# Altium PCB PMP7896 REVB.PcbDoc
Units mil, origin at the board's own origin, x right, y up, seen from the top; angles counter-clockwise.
Board outline 3850 x 3960 mil, 4 copper layers (Top Layer, MidLayer1, MidLayer2, Bottom Layer), stack 62.6 mil thick; 76 components, 29 nets, 152 pads, 108 vias.
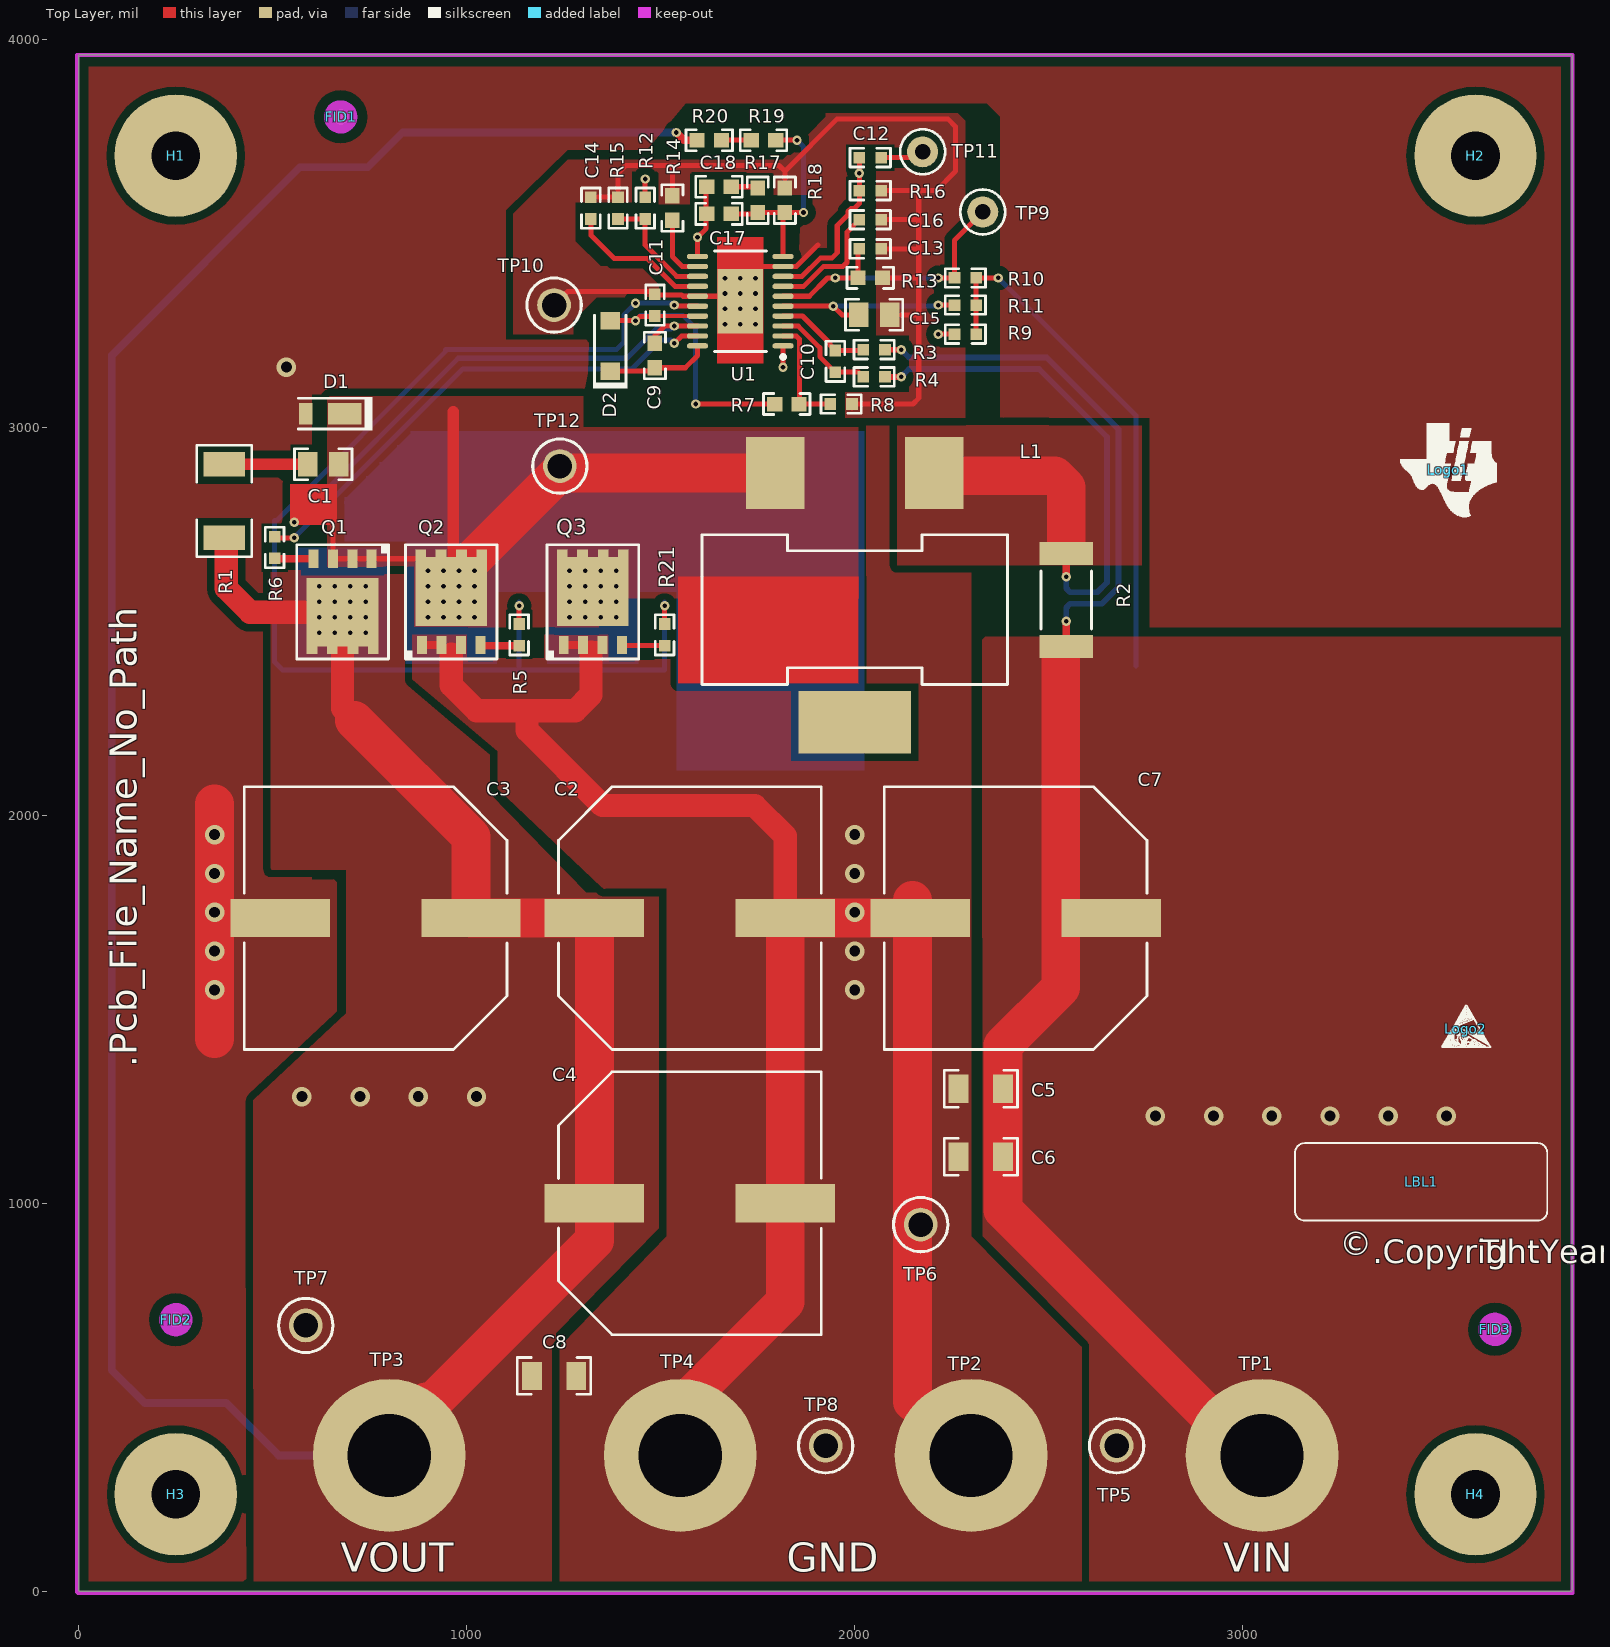
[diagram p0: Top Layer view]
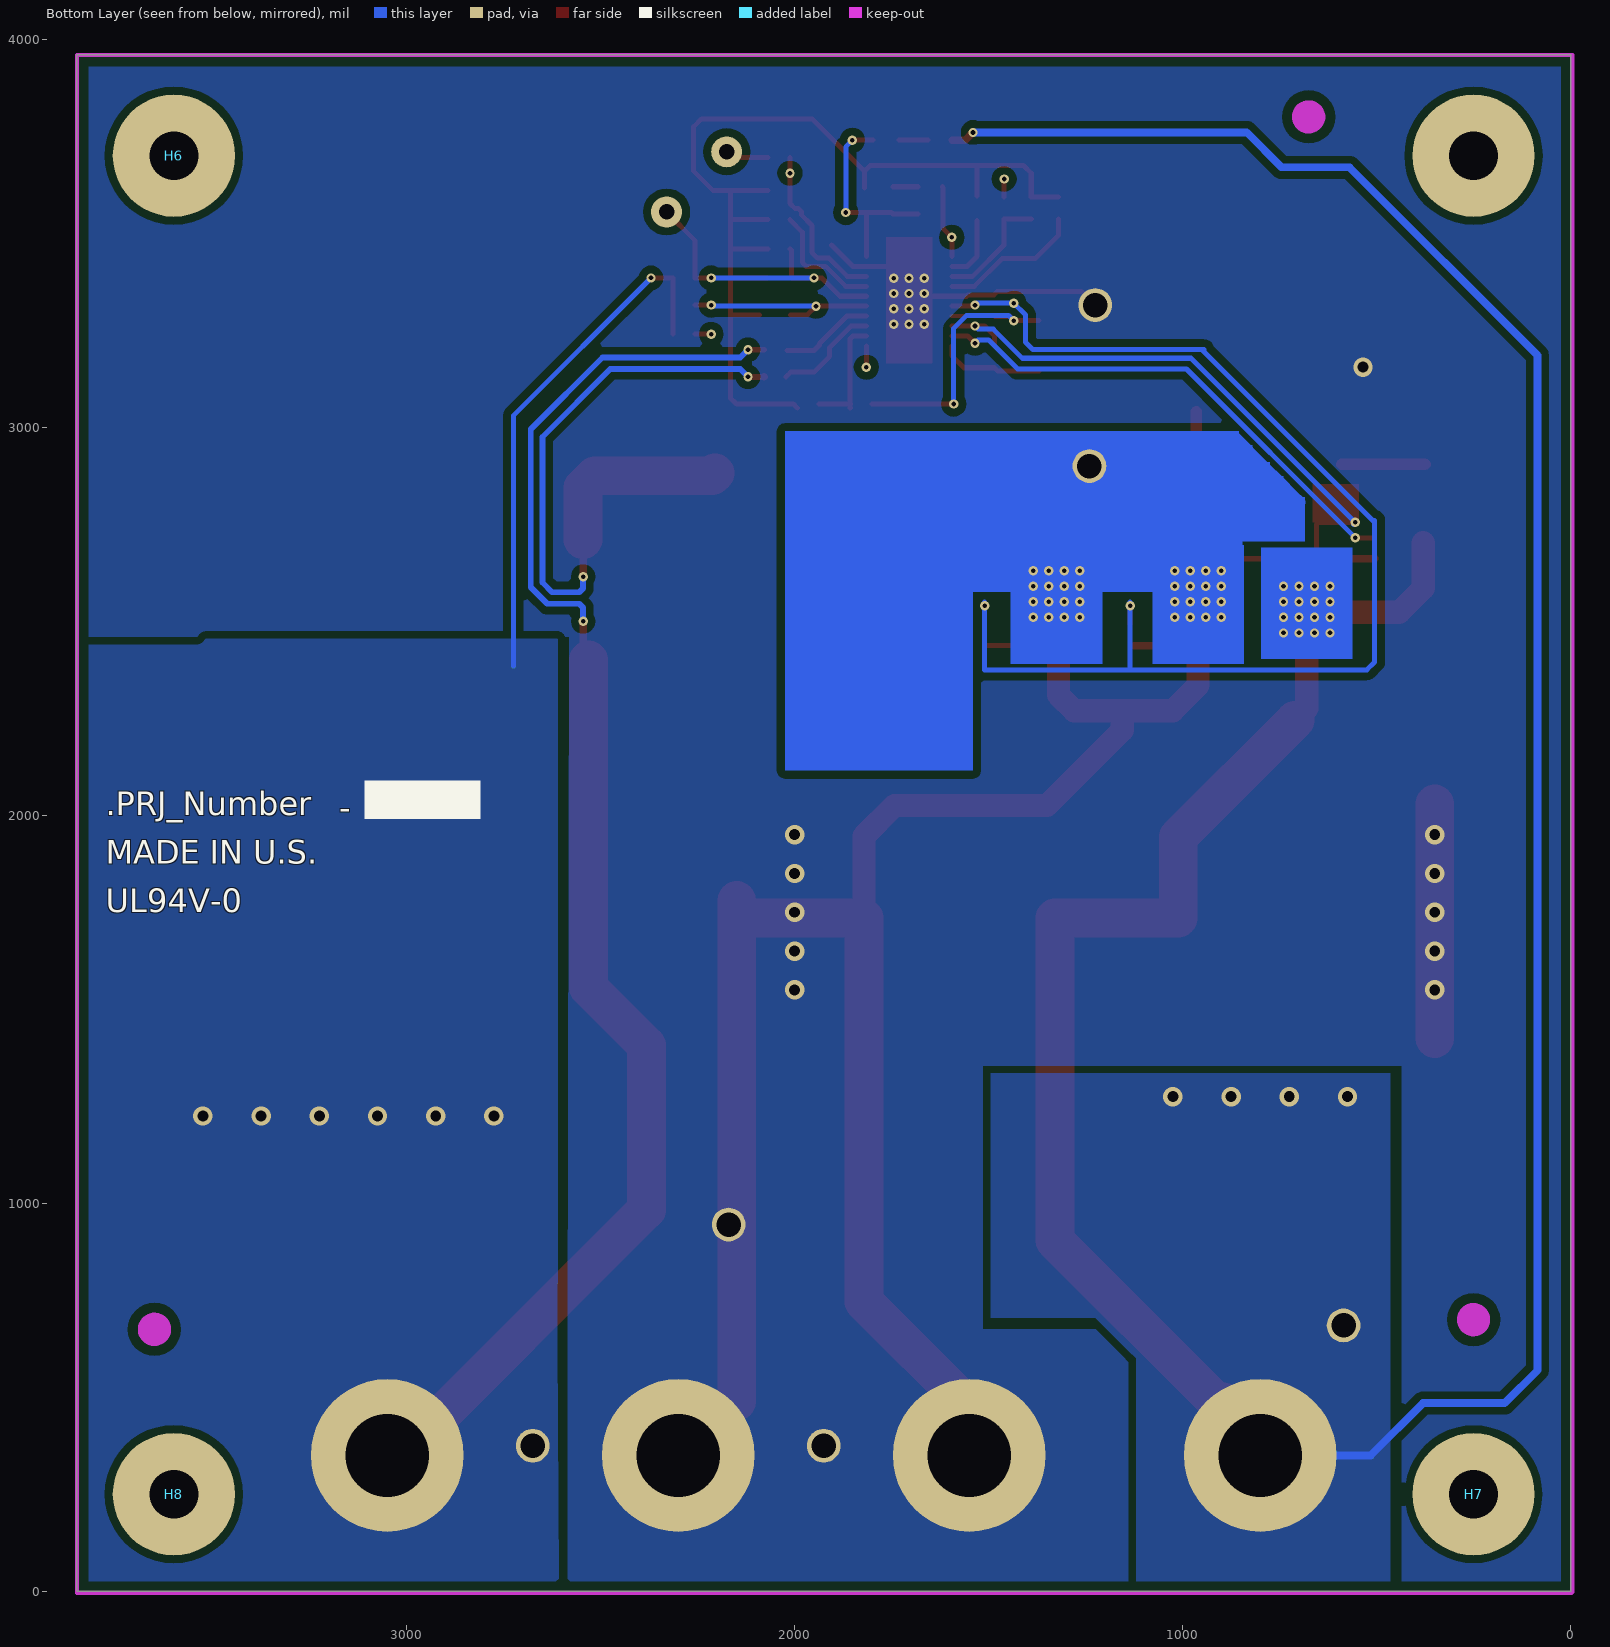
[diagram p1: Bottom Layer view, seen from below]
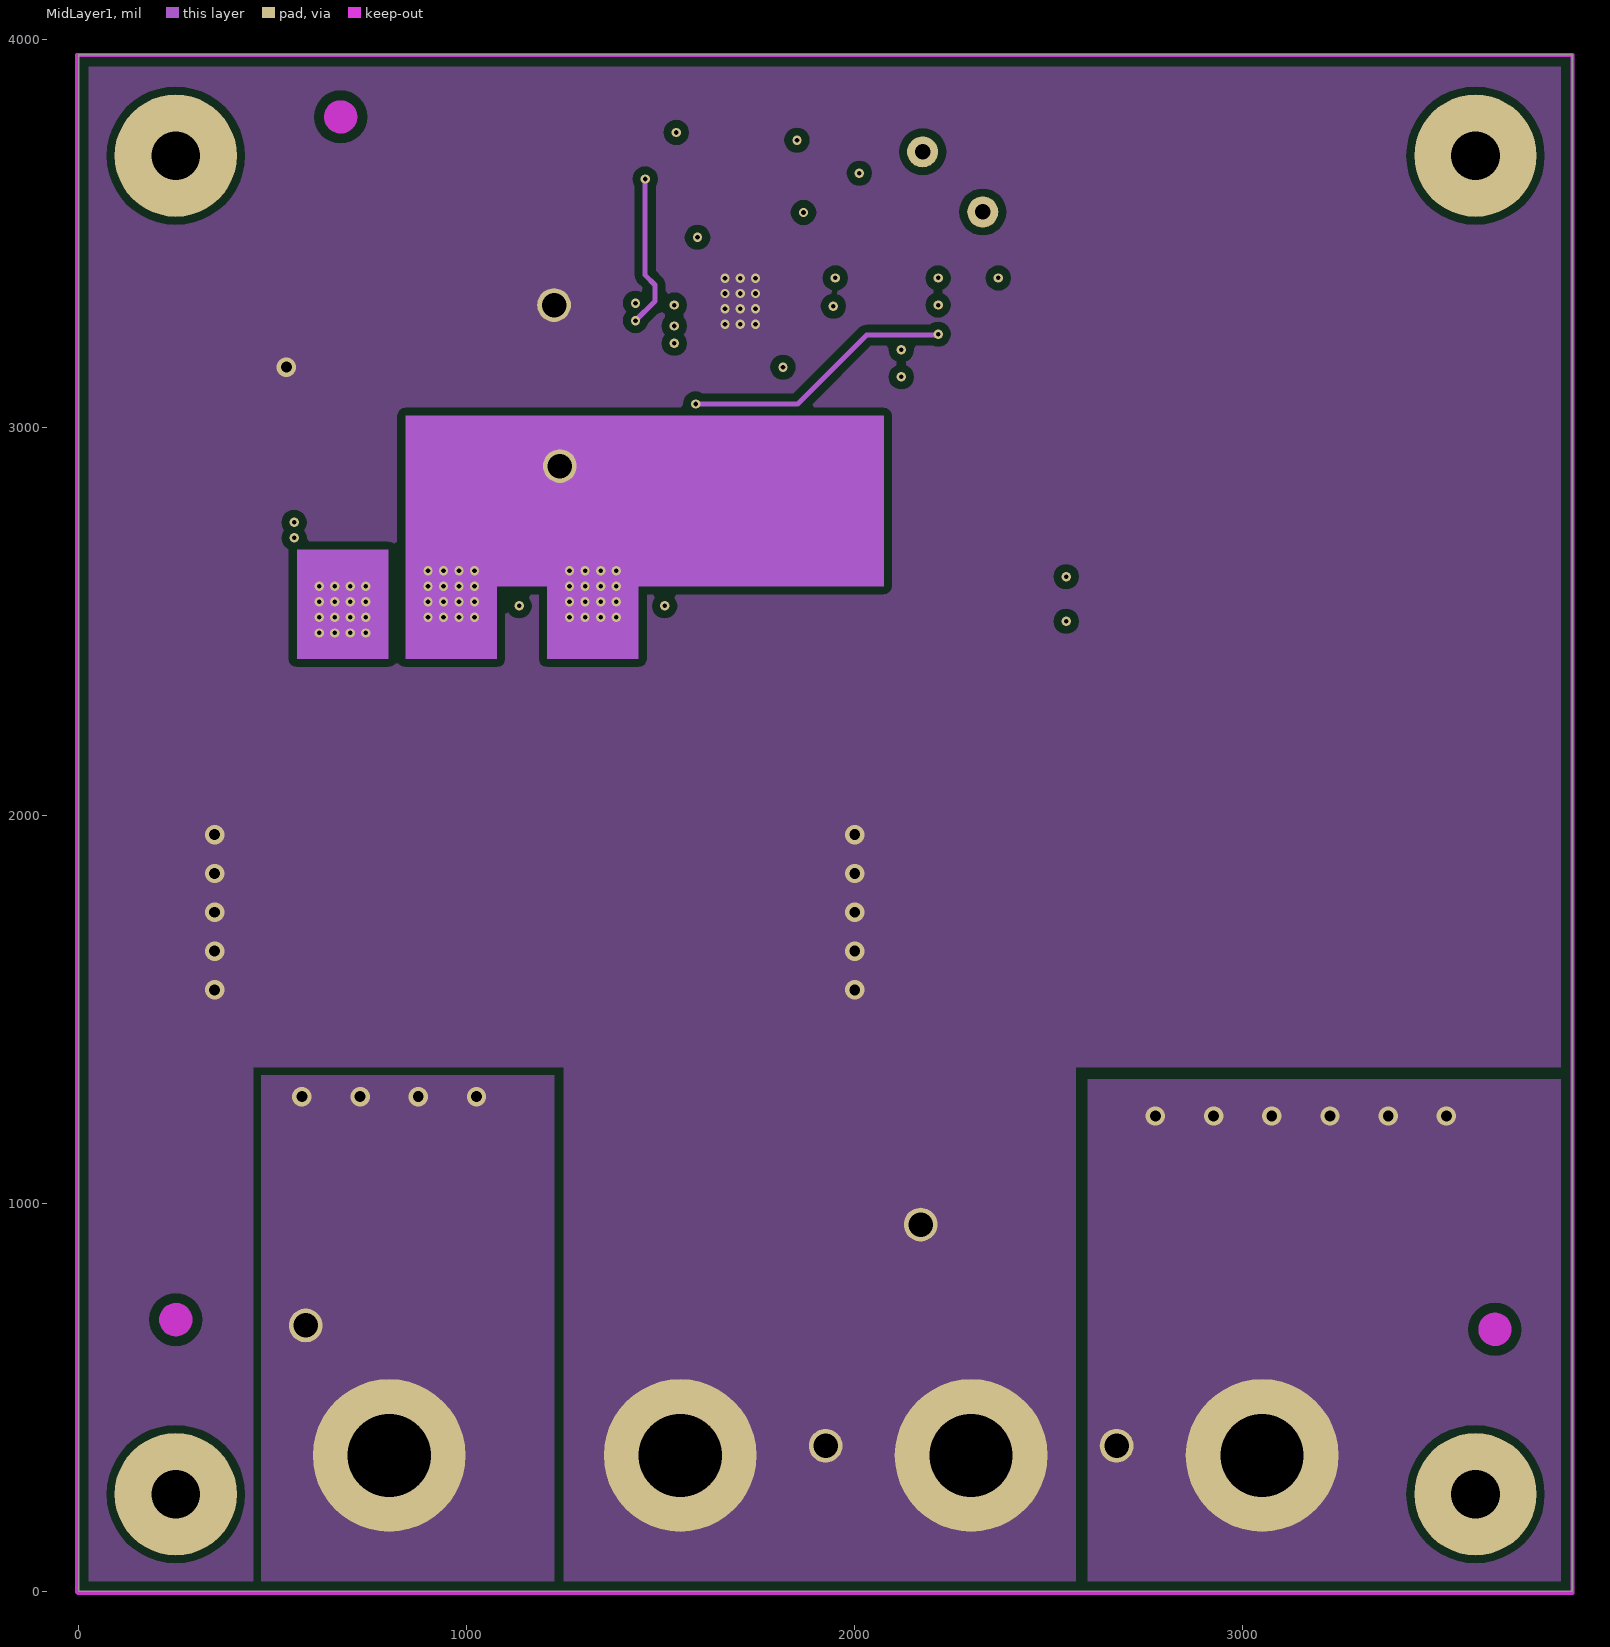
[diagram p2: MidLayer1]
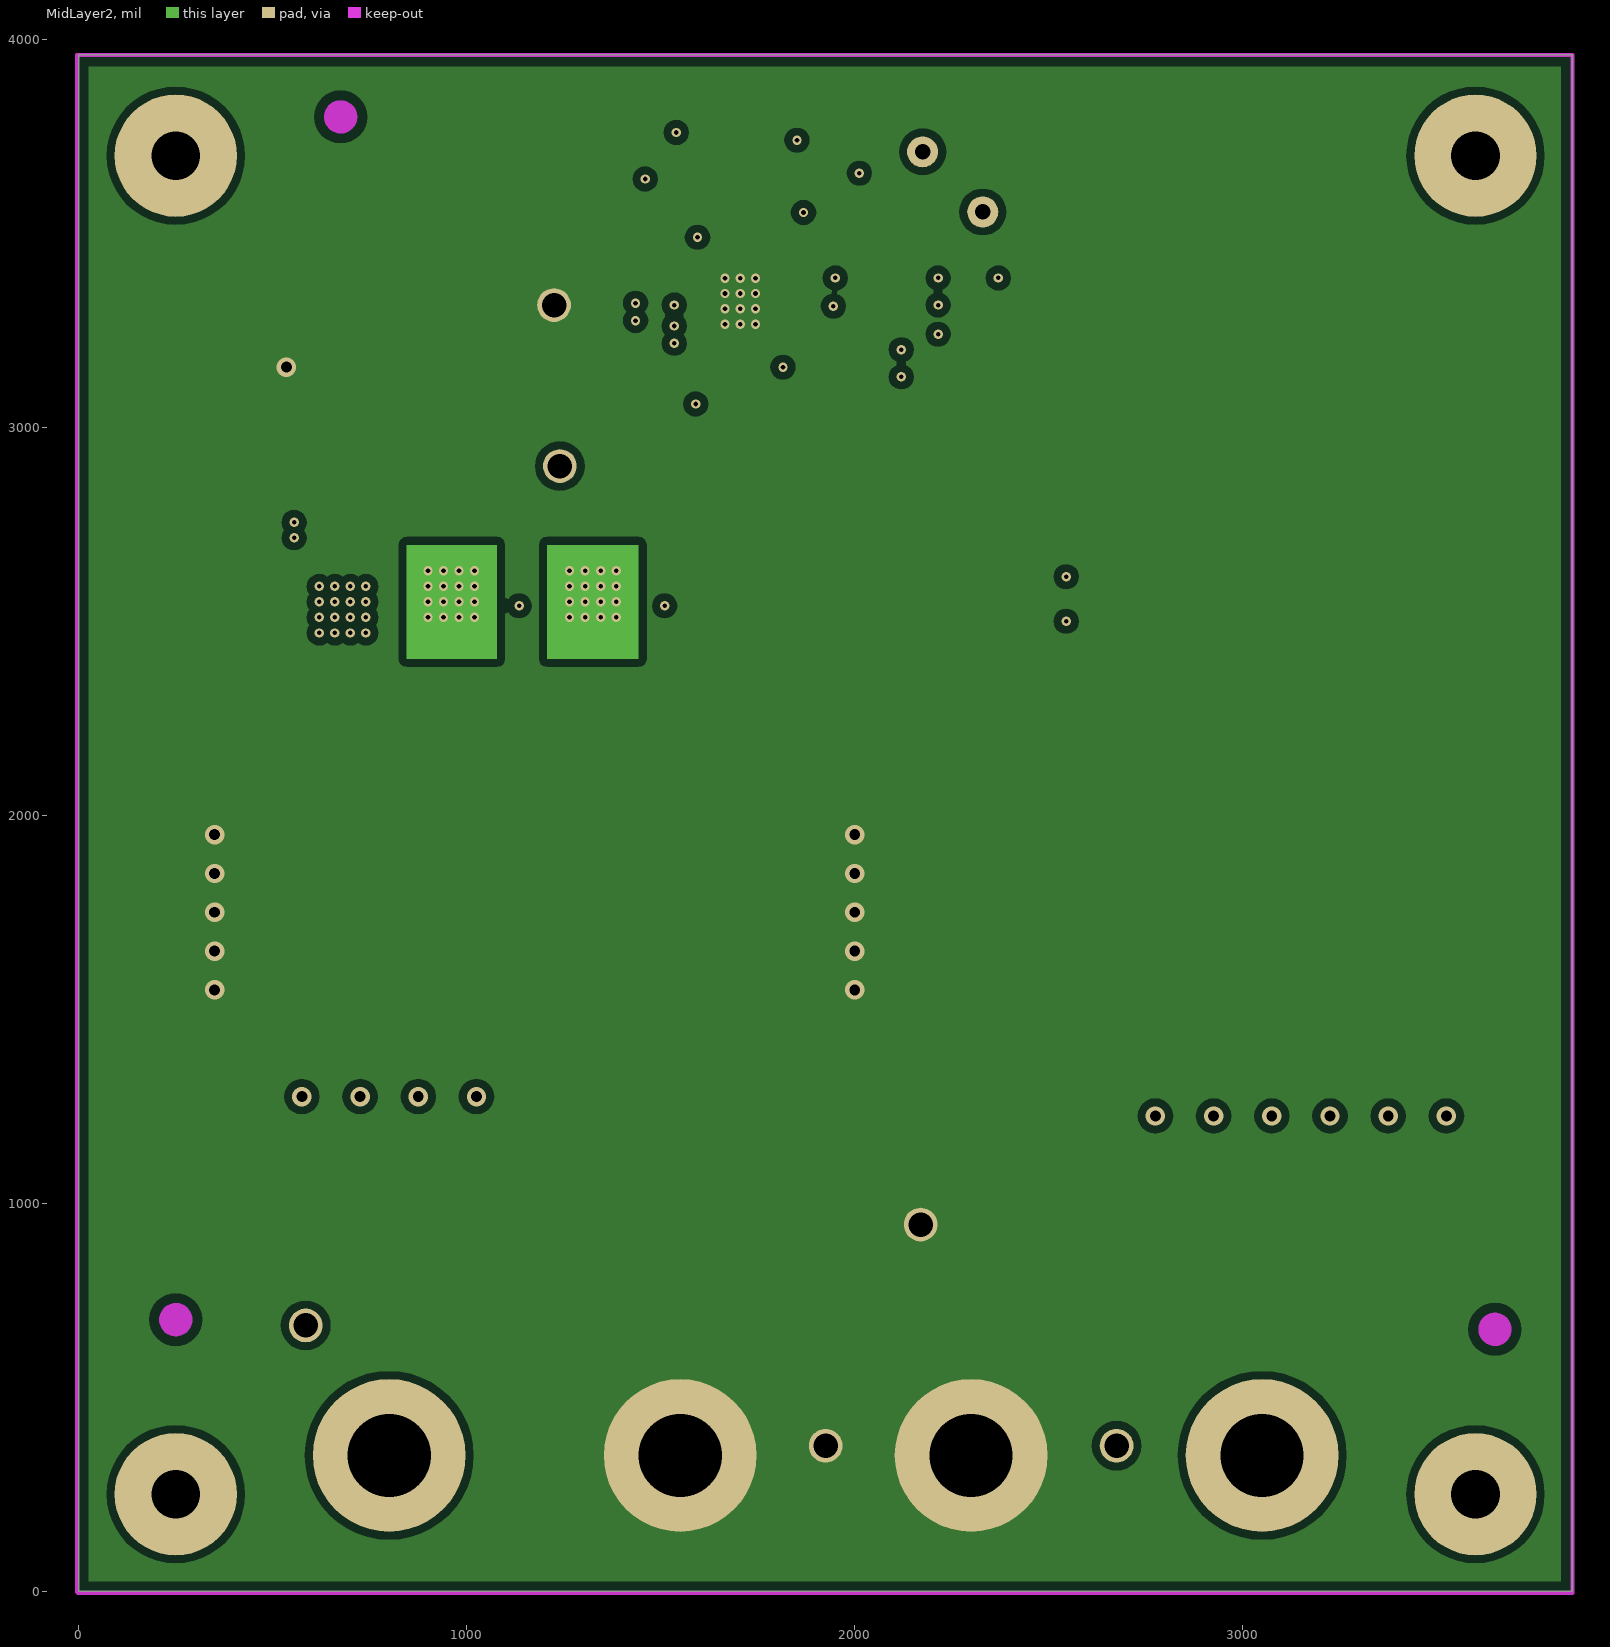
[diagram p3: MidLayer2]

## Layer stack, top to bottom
Top Layer: signal copper 1.4
Dielectric: prepreg 19, FR-4, Dk 4.8
MidLayer1: signal copper 1.4
Dielectric: core 19, FR-4, Dk 4.8
MidLayer2: signal copper 1.4
Dielectric: prepreg 19, FR-4, Dk 4.8
Bottom Layer: signal copper 1.4

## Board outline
0,0 0,3960 3850,3960 3850,0

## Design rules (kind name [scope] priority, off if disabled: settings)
AcuteAngle [All] p1: minimum=4.50000000000000E+0001 checktracksonly=FALSE
AssemblyTestPointUsage [All] p1: valid=2
Clearance Clearance_BoardEdge_MountingHoles [OnCopper and InComponentClass('Mounting Holes') vs IsKeepOut] p1: gap=40
Clearance Clearance_BoardEdge_Poly [OnCopper and InPoly vs IsKeepOut] p2: gap=25
Clearance Clearance_BoardEdge [OnCopper and Not InComponentClass('Logo') and not InComponentClass('FiducialMark') and not InRegion(1000,500,4000,800) vs IsKeepOut] p3: gap=75
Clearance Clearance_Polygon [IsRegion] p4: gap=20
Clearance [All] p5: gap=8
ComponentClearance ComponentClearance_Logo [InComponentClass(Logo)] p1: gap=50 collisioncheckmode=3 verticalgap=10 showdistances=FALSE
ComponentClearance ComponentClearance_ScrewToNut [(HasFootprint('NY PMS 440 0025 PH')) vs (HasFootprint('Keystone_1902C'))] p2: gap=5 collisioncheckmode=3 verticalgap=10 showdistances=FALSE
ComponentClearance ComponentClearance_MountingHoles [InComponentClass('Mounting Holes')] p3: gap=250 collisioncheckmode=3 verticalgap=100000 showdistances=FALSE
ComponentClearance ComponentClearance_SmallPassives [HasFootprint('0201*') or HasFootprint('0402*') or HasFootprint('0508') or HasFootprint('0603*') or HasFootprint('0612') or HasFootprint('0805*') or HasFootprint('0815*') or HasFootprint('0830*') or HasFootprint('1206*') or HasFootprint('1210*') or HasFootprint('1808*') or HasFootprint('1812*') or HasFootprint('1825*') or HasFootprint('2010*') or HasFootprint('2220*') or HasFootprint('2225*') or HasFootprint('2512*') or HasFootprint('2728*') or HasFootprint('3518*') vs HasFootprint('0201*') or HasFootprint('0402*') or HasFootprint('0508') or HasFootprint('0603*') or HasFootprint('0612') or HasFootprint('0805*') or HasFootprint('0815*') or HasFootprint('0830*') or HasFootprint('1206*') or HasFootprint('1210*') or HasFootprint('1808*') or HasFootprint('1812*') or HasFootprint('1825*') or HasFootprint('2010*') or HasFootprint('2220*') or HasFootprint('2225*') or HasFootprint('2512*') or HasFootprint('2728*') or HasFootprint('3518*')] p4: gap=20 collisioncheckmode=3 verticalgap=10 showdistances=FALSE
ComponentClearance ComponentClearance_THtoSMT [IsThruComponent vs IsSMTComponent] p5: gap=100 collisioncheckmode=3 verticalgap=100000 showdistances=FALSE
ComponentClearance ComponentClearance_THtoTH [IsThruComponent vs IsThruComponent] p6: gap=118.11 collisioncheckmode=3 verticalgap=100000 showdistances=FALSE
ComponentClearance [All] p7: gap=40 collisioncheckmode=3 verticalgap=10 showdistances=FALSE
DiffPairsRouting [All] p1: maxlimit=100 minlimit=10 mostfreqgap=15 maxuncoupledlength=1000
FabricationTestPointUsage TestPointUsage [All] p1: valid=2 allowmultiple=FALSE
FabricationTestpoint Testpoint [All] p1: side=3 testpointundercomponent=TRUE minsize=40 maxsize=100 preferedsize=60 minholesize=0 maxholesize=40 preferedholesize=32 testpointgrid=1 allowsidetop=TRUE allowsidebottom=TRUE usegrid=TRUE gridtolerance=0.01
FanoutControl Fanout_LCC [IsLCC] p1: bgadir=Out bgaviamode=Centered fanoutstyle=Auto fanoutdirection=Alternating viagrid=1 // Fanout_LCC (Default Rule)
FanoutControl Fanout_BGA [IsBGA] p2: bgadir=Out bgaviamode=Centered fanoutstyle=Auto fanoutdirection=Alternating viagrid=1 // Fanout_BGA (Default Rule)
FanoutControl Fanout_Default [All] p4: bgadir=Out bgaviamode=Centered fanoutstyle=Auto fanoutdirection=Alternating viagrid=1 // Fanout_Default (Default Rule)
FanoutControl Fanout_Small [(CompPinCount < 5)] p5: bgadir=Out bgaviamode=Centered fanoutstyle=Auto fanoutdirection=OutThenIn viagrid=1 // Fanout_Small (Default Rule)
HoleSize [All] p1: absolutevalues=TRUE maxlimit=251 minlimit=10 maxpercent=80.000 minpercent=20.000
MinimumAnnularRing [All] p1: minimumring=6
MinimumSolderMaskSliver MinimumSolderMaskSliver_Logo [InComponentClass('Logo') vs InComponentClass('Logo')] p1: minsoldermaskwidth=0.7
MinimumSolderMaskSliver [All] p2: minsoldermaskwidth=4
PlaneConnect [All] p1: planeconnectstyle=Relief reliefexpansion=10 reliefentries=4 reliefconductorwidth=10 reliefairgap=10
PolygonConnect [All] p1: connectstyle=Direct reliefconductorwidth=10 reliefentries=4 polygonreliefangle="90 Angle" airgapwidth=10
RoomDefinition "PMP7896 Rev3A Schematic" [InComponentClass('PMP7896 Rev3A Schematic')] p1 off: confinementstyle=ConfineIn formatcopy=TRUE lockcomponents=FALSE outline -692,-1534 1308,-1534 1308,-534 -692,-534
RoutingVias [All] p1: holewidth=12 width=24 viastyle="Through Hole" minholewidth=10 minwidth=24 maxholewidth=28 maxwidth=50
SMDToCorner [All] p1: distance=30000
SilkToSilkClearance [All] p1: silktosilkclearance=5
SilkscreenOverComponentPads [All] p1: minsilkscreentomaskgap=5
SolderMaskExpansion [All] p1: expansion=3
Width Width_SW_P [InNet('SW_P')] p1: maxlimit=100 minlimit=10 preferedwidth=15
Width Width_SW_N [InNet('SW_N')] p2: maxlimit=100 minlimit=10 preferedwidth=15
Width Width_CSP_P [InNet('CSP_P')] p3: maxlimit=100 minlimit=10 preferedwidth=15
Width Width_CSP_N [InNet('CSP_N')] p4: maxlimit=100 minlimit=10 preferedwidth=15
Width Width_CSPP_N [InNet('CSPP_N')] p5: maxlimit=100 minlimit=15 preferedwidth=15
Width Width_CSPP_P [InNet('CSPP_P')] p6: maxlimit=100 minlimit=15 preferedwidth=15
Width [All] p7: maxlimit=100 minlimit=6 preferedwidth=10 checkconnectedcopper=TRUE
14 further rules are at their usual default settings.

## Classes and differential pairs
component class "PMP7896 Rev3A Schematic": C1 C2 C3 C4 C5 C6 C7 C8 C9 C10 C11 C12 C13 C14 C15 C16 C17 C18 D1 D2 L1 Q1 Q2 Q3 R1 R2 R3 R4 R5 R6 R7 R8 R9 R10 R11 R12 R13 R14 R15 R16 R17 R18 R19 R20 R21 TP1 TP2 TP3 TP4 TP5 TP6 TP7 TP8 TP9 TP10 TP11 TP12 U1
component class "Mounting Holes": H1 H2 H3 H4
component class Logo: Logo1
component class Hardware_ANSI-B: FID1 FID2 FID3 H1 H2 H3 H4 H5 H6 H7 H8 LBL1 Logo1 Logo2 ZZ1 ZZ2 ZZ3 ZZ4
component class FiducialMark: FID1 FID2 FID3
component class AssemblyNote: ZZ1 ZZ2 ZZ3 ZZ4
component class Label: LBL1
differential pair CSP: +CSP_P -CSP_N
differential pair SW: +SW_P -SW_N

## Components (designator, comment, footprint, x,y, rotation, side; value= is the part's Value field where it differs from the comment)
C1 "GRM2165C2A471JA01D" 0805_HV 630,2905 r0 top
C2 "EEV-FK2A101M" SM_RADIAL_J16 1575,1735 r0 top
C3 "EEV-FK2A101M" SM_RADIAL_J16 765,1735 r180 top
C4 "EEV-FK2A101M" SM_RADIAL_J16 1575,1000 r0 top
C5 "C3216X7R2A105M" 1206 2325,1295 r180 top
C6 "C3216X7R2A105M" 1206 2325,1120 r180 top
C7 "EMVH101GDA101MLH0S" SM_RADIAL_J16 2415,1735 r180 top
C8 "C3216X7R2A105M" 1206 1225,555 r0 top
C9 "GRM188R72A104KA35D" 0603 1485,3185 r270 top
C10 "GRM1885C1H101JA01D" 0603_HV 1950,3170 r90 top
C11 "4.7µF" 0603_HV 1485,3315 r270 top
C12 "GRM1885C1H101JA01D" 0603_HV 2040,3695 r0 top
C13 "GRM1885C1H101JA01D" 0603_HV 2040,3460 r0 top
C14 "GRM188R71E473KA01D" 0603_HV 1320,3565 r90 top
C15 "GRM21BR72A474KA73L" 0805_HV 2050,3290 r0 top
C16 "GRM188R71E104KA01D" 0603_HV 2040,3535 r0 top
C17 "C1608C0G1H331J" 0603 1650,3550 r180 top
C18 "C1608X7R1H223K" 0603 1650,3620 r180 top
D1 "DNP" powerDI123 635,3035 r180 top
D2 "MBR1H100SFT3G" SOD-123FL 1370,3210 r90 top
FID1 "Fiducial" Fiducial10-20 675,3800 r0 top
FID2 "Fiducial" Fiducial10-20 250,700 r0 top
FID3 "Fiducial" Fiducial10-20 3650,675 r0 top
H1 "NY PMS 440 0025 PH" "NY PMS 440 0025 PH" 250,3700 r0 top
H2 "NY PMS 440 0025 PH" "NY PMS 440 0025 PH" 3600,3700 r0 top
H3 "NY PMS 440 0025 PH" "NY PMS 440 0025 PH" 250,250 r0 top
H4 "NY PMS 440 0025 PH" "NY PMS 440 0025 PH" 3600,250 r0 top
H5 "1902C" Keystone_1902C 250,4170 r0 top
H6 "1902C" Keystone_1902C 3600,3700 r180 bottom locked
H7 "1902C" Keystone_1902C 250,250 r180 bottom
H8 "1902C" Keystone_1902C 3600,250 r180 bottom locked
L1 "SER2014-402MLB" SER2014 2000,2530 r270 top
LBL1 "Size: 0.65\" x 0.20 \"" Label_650x200 3460,1055 r0 top
Logo1 "Texas Instruments" TI_Symbol_Overlay_Medium 3530,2890 r0 top
Logo2 "ESD Susceptible" ESD_Overlay_Small 3575,1450 r0 top
Q1 "Infineon, BSC123N08NS3 G" "PG-TDSON-8 WITH VIAS" 680,2550 r270 top
Q2 "Infineon, BSC123N08NS3 G" "PG-TDSON-8 WITH VIAS" 960,2550 r90 top
Q3 "Infineon, BSC123N08NS3 G" "PG-TDSON-8 WITH VIAS" 1325,2550 r90 top
R1 "ERJ-12ZYJ7R5U" 2010M 375,2810 r270 top
R2 "ERJ-M1WSF4M0U" 2512M 2545,2555 r90 top
R3 "ERJ-3GEY0R00V" 0603_HV 2050,3200 r0 top
R4 "ERJ-3GEY0R00V" 0603_HV 2050,3130 r0 top
R5 "ERJ-3GEY0R00V" 0603_HV 1135,2465 r90 top
R6 "ERJ-3GEY0R00V" 0603_HV 505,2690 r270 top
R7 "CRCW0603158KFKEA" 0603 1825,3060 r180 top
R8 "ERJ-3GEY0R00V" 0603_HV 1965,3060 r180 top
R9 "CRCW06033R30JNEA" 0603_HV 2285,3240 r180 top
R10 "CRCW060349K9FKEA" 0603_HV 2285,3385 r0 top
R11 "CRCW06033R30JNEA" 0603_HV 2285,3315 r0 top
R12 "ERJ-3GEY0R00V" 0603_HV 1460,3565 r90 top
R13 "CRCW06038K66FKEA" 0603 2040,3385 r180 top
R14 "CRCW060310K0FKEA" 0603 1530,3565 r270 top
R15 "ERJ-3GEY0R00V" 0603_HV 1390,3565 r270 top
R16 "CRCW060340K2FKEA" 0603_HV 2040,3610 r180 top
R17 "CRCW060359K0FKEA" 0603 1750,3585 r90 top
R18 "CRCW06032K26FKEA" 0603 1820,3585 r90 top
R19 "CRCW060384K5FKEA" 0603 1765,3740 r180 top
R20 "CRCW06033R48FKEA" 0603 1625,3740 r0 top
R21 "ERJ-3GEY0R00V" 0603_HV 1510,2465 r90 top
TP1 "575-8" Keystone575-8 3050,350 r0 top
TP2 "575-8" Keystone575-8 2300,350 r0 top
TP3 "575-8" Keystone575-8 800,350 r0 top
TP4 "575-8" Keystone575-8 1550,350 r0 top
TP5 "5010" Keystone5010 2675,375 r0 top
TP6 "5011" Keystone5011 2170,945 r0 top
TP7 "5010" Keystone5010 585,685 r0 top
TP8 "5011" Keystone5011 1925,375 r0 top
TP9 "5002" Keystone5002 2330,3555 r0 top
TP10 "5011" Keystone5011 1225,3315 r0 top
TP11 "5002" Keystone5002 2175,3710 r0 top
TP12 "5012" Keystone5012 1240,2900 r0 top
U1 "LM5122MH" MXA20A_L 1705,3325 r180 top
ZZ1 "This Assembly Note is for PCB labels only" AssemblyNoteLabel 265,6538 r0 top
ZZ2 "These assemblies are ESD sensitive, ESD precautions shall be observed." AssemblyNote 265,6429.11 r0 top
ZZ3 "These assemblies must be clean and free from flux and all contaminants. Use of no clean flux is not acceptable." AssemblyNote 265,6340.56 r0 top
ZZ4 "These assemblies must comply with workmanship standards IPC-A-610 Class 2., unless otherwise specified." AssemblyNote 265,6252 r0 top

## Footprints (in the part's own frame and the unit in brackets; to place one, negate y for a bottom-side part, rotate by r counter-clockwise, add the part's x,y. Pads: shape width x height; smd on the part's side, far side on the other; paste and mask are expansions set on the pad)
0603 [mm] "0603 from SM-752 data"
  rect 1x0.95 smd: 1(-0.8,0) 2(0.8,0)
  silkscreen extent -1.52,-0.69 1.52,0.69, body extent -0.87,-0.47 0.87,0.47, height 0.85
0603_HV [mil] "Ernesto recommended land pattern.  26 mil between pads."
  rect 30x30 smd: 1(-28,0) 2(28,0)
  silkscreen extent -52,-24 52,24, body extent -34,-19 34,19, height 33
0805_HV [mil] "0805 with 30mil clearance between pads"
  rect 50x63 smd: 1(-40,0) 2(40,0)
  silkscreen extent -74,-40 74,40, body extent -43,-29 43,29, height 43
1206 [mm] "1206 from SM-752 data"
  rect 1.3x1.85 smd: 1(-1.45,0) 2(1.45,0)
  silkscreen extent -2.4,-1.21 2.4,1.21, body extent -1.7,-0.9 1.7,0.9, height 1.35
2010M [mm]
  rect 1.6x2.7 smd: 1(-2.4,0) 2(2.4,0)
  silkscreen extent -3.65,-1.8 3.65,1.8, body extent -2.73,-1.45 2.73,1.45, height 1.66
2512M [mm] "Chip Resistor, Body 6.3x3.2mm, IPC Low Density"
  rect 1.5x3.5 smd: 1(-3.05,0) 2(3.05,0)
  silkscreen extent -1.9,-1.65 1.9,1.65, body extent -3.22,-1.67 3.22,1.67, height 0.71
AssemblyNote [mil] "Assembly Note"
AssemblyNoteLabel [mil] "Assembly Note for PCB Labels"
ESD_Overlay_Small [mil]
  silkscreen extent -62,-48 64,61
Fiducial10-20 [mm]
  round 1 smd paste-0.5 mask+0.5: 1(0,0)
  Keep-Out Layer circle w1.178: c0,0 r0.5
Keystone575-8 [mm] "Banana Jack"
  round 10 hole 5.45: 1(0,0)
  body extent -3.92,-3.94 3.95,3.94, height 2.36
Keystone5002 [mil] "For Keystone 500x miniature loop terminals"
  round 80 hole 40: 1(0,0)
  silkscreen extent -58,-58 58,58, body extent -49,-49 49,49, height 182
Keystone5010 [mil] "Keystone Multipurpose loops"
  round 87 hole 63: 1(0,0)
  silkscreen extent -70,-70 70,70, body extent -63,-63 63,62, height 319
Keystone5011 [mil] "Keystone Multipurpose loops"
  round 87 hole 63: 1(0,0)
  silkscreen extent -70,-70 70,70, body extent -63,-63 63,62, height 319
Keystone5012 [mil] "Keystone Multipurpose loops"
  round 87 hole 63: 1(0,0)
  silkscreen extent -70,-70 70,70, body extent -63,-63 63,62, height 319
Keystone_1902C [mil] "Hex Standoff, 4-40 threaded, nylon"
  body extent -145,-126 146,126, height 501
Label_650x200 [mil] "Thermal Transfer Label"
  silkscreen extent -325,-100 325,100, body extent -326,-101 326,101, height 1
MXA20A_L [mm] "TSOP, 20-Leads, Body 6.5x4.4mm, Pitch 0.65mm, Exposed Pad, IPC High Density"
  oval 1.4x0.35 smd: 1(-2.8,2.925) 2(-2.8,2.275) 3(-2.8,1.625) 4(-2.8,0.975) 5(-2.8,0.325) 6(-2.8,-0.325) 7(-2.8,-0.975) 8(-2.8,-1.625) 9(-2.8,-2.275) 10(-2.8,-2.925) 11(2.8,-2.925) 12(2.8,-2.275) 13(2.8,-1.625) 14(2.8,-0.975) 15(2.8,-0.325) 16(2.8,0.325) 17(2.8,0.975) 18(2.8,1.625) 19(2.8,2.275) 20(2.8,2.925)
  rect 3x4.2 smd: 21(0,0)
  silkscreen extent -2.93,-3.3 1.7,3.77, body extent -2.25,-3.3 2.25,3.3, height 1.1
"NY PMS 440 0025 PH" [mm] "4-40 nylon screw and mounting hole"
  round 8 hole 3.2: 1(0,0)
  body extent -3.3,-3.3 3.3,3.3, height 2.69
"PG-TDSON-8 WITH VIAS" [mm] "Infineon recommended land pattern"
  rect 1.2x0.65 smd: 1(-2.825,1.905) 2(-2.825,0.635) 3(-2.825,-0.635) 4(-2.825,-1.905)
  rect 0.5x0.7 smd: 5(3.175,-2) 6(3.175,-0.675) 7(3.175,0.675) 8(3.175,2)
  rect 4.5x4.7 smd paste-2.25: 9(0.675,0)
  silkscreen extent -3.74,-3 3.74,3, body extent -3.18,-2.89 3.18,2.9, height 1.1
powerDI123 [mm] "Diodes Inc recommended land pattern, document number DS30628 Rev. 6-2"
  rect 2.2x1.4 smd: 1(-1.275,0)
  rect 0.9x1.4 smd: 2(1.275,0)
  silkscreen extent -3.1,-1.09 1.76,1.09, body extent -2.38,-0.97 1.52,0.96, height 1
SER2014 [mil] "Coilcraft recommended land pattern.  Document 349-1, rev 02/24/10"
  rect 185x150 smd: 1(-352.25,205) 2(-352.25,-205)
  rect 160x290 smd: 3(290.25,0)
  silkscreen extent -193,-394 193,394, body extent -412,-390 324,390, height 550
SM_RADIAL_J16 [mm] "16 x 16.5mm:  Panasonic J16"
  rect 6.5x2.5 smd: 1(-6.25,0) 2(6.25,0)
  silkscreen extent -8.6,-8.6 8.6,8.6, body extent -8.6,-8.6 8.6,8.6, height 17
SOD-123FL [mil] "On Semiconductor r"
  rect 45x50 smd paste-1.97: 1(-65,0) 2(65,0)
  silkscreen extent -110,-44 79,44, body extent -71,-33 71,33, height 47
TI_Symbol_Overlay_Medium [mil]
  silkscreen extent -124,-122 124,120

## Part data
C1: "CAP, CERM, 470pF, 100V, +/-5%, C0G/NP0, 0805"
C2 C3 C4: "CAP, AL, 100uF, 100V, +/-20%, 0.17 ohm, SMD"
C5 C6 C8: "CAP, CERM, 1uF, 100V, +/-20%, C Series, 1206"
C7: "CAP ALUM 100UF 100V 20% SMD"
C9: "CAP, CERM, 0.1uF, 100V, +/-10%, X7R, 0603"
C10 C12 C13: "CAP, CERM, 100pF, 50V, +/-5%, C0G/NP0, 0603"
C11: library part C1608X6S1A475K, "CAP CER 4.7UF 10V 10% X6S 0603"
C14: "CAP, CERM, 0.047uF, 25V, +/-10%, X7R, 0603"
C15: "CAP, CERM, 0.47uF, 100V, +/-10%, X7R, 0805"
C16: "CAP, CERM, 0.1uF, 25V, +/-10%, X7R, 0603"
C17: "CAP, CERM, 330pF, 50V, +/-5%, C0G/NP0, 0603"
C18: "CAP, CERM, 0.022uF, 50V, +/-10%, X7R, 0603"
D1: library part DFLS1100-7, "Diode, Schottky, 100V, 1A, PowerDI123"
D2: "DIODE SCHOTTKY 1A 100V SOD-123FL"
FID1 FID2 FID3: "Fiducial mark.  There is nothing to buy or mount."
H1 H2 H3 H4: "Machine Screw, Round, #4-40 x 1/4, Nylon, Philips panhead"
H5 H6 H7 H8: "Standoff, Hex, 0.5\"L #4-40 Nylon"
L1: "Inductor, Shielded E Core, Ferrite, 4uH, 25A, 0.00194 ohm, SMD"
LBL1: library part THT-14-423-10, "Thermal Transfer Printable Labels, 0.650\" W x 0.200\" H - 10,000 per roll"
Logo1: library part TI_Logo, "Texas Instrument Corporate Signature"
Logo2: library part ESD_Susceptible, "ESD Susceptible Symbol"
Q1 Q2 Q3: library part "BSC123N08NS3 G", "MOSFET, N-CH, 80V, 55A, PG-TDSON-8"
R1: "RESISTOR 7.5 OHM 3/4W 5% 2010"
R2: "RES, 0.004 ohm, 1%, 1W, 2512"
R3 R4 R5 R6 R8 R12 R15 R21: "RES, 0 ohm, 5%, 0.1W, 0603"
R7: "RES, 158k ohm, 1%, 0.1W, 0603"
R9 R11: "RES, 3.3 ohm, 5%, 0.1W, 0603"
R10: "RES, 49.9k ohm, 1%, 0.1W, 0603"
R13: "RES, 8.66k ohm, 1%, 0.1W, 0603"
R14: "RES, 10.0k ohm, 1%, 0.1W, 0603"
R16: "RES, 40.2k ohm, 1%, 0.1W, 0603"
R17: "RES, 59.0k ohm, 1%, 0.1W, 0603"
R18: "RES, 2.26k ohm, 1%, 0.1W, 0603"
R19: "RES, 84.5k ohm, 1%, 0.1W, 0603"
R20: "RES, 3.48 ohm, 1%, 0.1W, 0603"
TP1 TP2 TP3 TP4: "Standard Banana Jack, Uninsulated, 8.9mm"
TP5 TP7: "Test Point, TH, Multipurpose, Red"
TP6 TP8 TP10: "Test Point, TH, Multipurpose, Black"
TP9 TP11: "Test Point, TH, Miniature, White"
TP12: "Test Point, TH, Multipurpose, White"
U1: library part LM5122
ZZ1: library part AssemblyNoteLabel
ZZ2 ZZ3 ZZ4: library part AssemblyNote

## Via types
v1: diameter 24, hole 12, Top Layer to Bottom Layer, 87 vias
v2: diameter 50, hole 28, Top Layer to Bottom Layer, 21 vias

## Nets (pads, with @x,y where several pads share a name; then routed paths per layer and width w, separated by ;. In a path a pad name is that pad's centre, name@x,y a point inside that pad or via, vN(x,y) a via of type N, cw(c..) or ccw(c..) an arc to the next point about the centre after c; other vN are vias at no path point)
BST: C9.2 D2.1 U1.20 | length 266.3
  Top Layer w13: D2.1 1476.5,3145 C9.2 1563.5,3153.5 1594.76,3184.76 U1.20
COMP: C17.2 C18.2 U1.11 | length 189.7
  Top Layer w13: U1.11 v1(1594.76,3489.76) 1616.99,3511.99 1616.99,3618.48 C18.2
CSP_N: C10.1 R4.1 U1.3 | length 274.3
  Top Layer w13: U1.3@1815.24,3260.61 1854.39,3260.61 1910,3205 1910,3182 C10.1 2010,3142 R4.1
CSP_P: C10.2 R3.1 U1.4 | length 243.7
  Top Layer w13: U1.4 1865.16,3286.61 1936,3215.77 1936,3212 C10.2 R3.1@2020,3198
CSPP_N: L1.1 R2.2 R4.2 | length 1727.8
  Top Layer w15: R4.2 v1(2120,3130)
  Top Layer w20: v1(2545,2615) R2.2
  Top Layer w100: L1.1 2212.25,2875 2515,2875 2545,2845 2545,2710
  Bottom Layer w15: v1(2120,3130) 2140,3150 2475,3150 2650,2975 2650,2600 2625,2575 2555,2575 2545,2585 v1(2545,2615)
EXT_SYNC: C12.2 TP11.1 | length 113.2
  Top Layer w13: C12.2 2160,3695 TP11.1
FB: C17.1 R17.1 R18.1 R19.1 U1.10 | length 550.3
  Top Layer w13: C17.1 1746.5,3550 R17.1 R18.1 ; R19.1@1797.52,3740 v1(1851.02,3740) ; U1.10 1815.24,3548.74 R18.1 ; v1(1868,3553.5) R18.1
  Bottom Layer w13: v1(1851.02,3740) 1868,3723.02 v1(1868,3553.5)
GND: C2.2 C3.2 C4.2 C5.2 C6.2 C7.2 C8.2 C11.1 C13.2 C14.2 C15.2 C16.2 D1.2 Q2.1 Q2.2 Q2.3 Q3.1 Q3.2 Q3.3 R8.1 R13.1 R14.1 R15.1 R16.1 R18.2 TP2.1 TP4.1 TP6.1 TP8.1 TP10.1 U1.9 U1.15 U1.21 | length 8627.6
  Top Layer w13: TP10.1 1260,3350 1478,3350 C11.1@1486.5,3341.5 ; C14.2 R15.1 1390,3655 1410,3675 1530,3675 ; C11.1 C11.1@1486.5,3341.5 ; R14.1 1530,3675 ; U1.21@1658.74,3337.8 U1.15 1557.2,3337.8 1553.5,3341.5 C11.1@1486.5,3341.5 ; 1735.43,3414.57 U1.9 1849.57,3414.57 1905,3470 ; R18.2 1820,3660 ; R8.1@1993,3050 2003,3060 2150,3060 2165,3075 2165,3290 ; C13.2 2165,3460 ; C16.2 2165,3535 ; R16.1 2210,3610 2260,3660 2260,3775 2240,3795 1955,3795 1820,3660 ; R13.1 2165,3385 ; C15.2 2165,3290 ; 2165,3610 2165,3535 ; 1530,3675 1805,3675 1820,3660 ; 2165,3290 2165,3385 ; 2165,3385 2165,3460 ; 2165,3460 2165,3535
  Top Layer w20: Q2.1 Q2.2 ; Q3.1 Q3.2 Q3.3
  Top Layer w60: 960,2415 960,2335 1025.51,2269.49 1155.51,2269.49 ; 1320,2420 1320,2310 1279.49,2269.49 1155.51,2269.49 ; C2.2 1821.06,1946.59 1742.65,2025 1350,2025 1155.51,2219.49 1155.51,2269.49
  Top Layer w100: 350,1425 350,2028.94 ; TP4.1@1550,475 1821.06,746.06 C4.2 C2.2 C7.2@2139.06,1735 ; 2149.06,488.94 C7.2@2149.06,1780
  other v1: 1665.63,3265.94 1705,3265.94 1744.37,3265.94 1665.63,3305.31 1705,3305.31 1744.37,3305.31 1665.63,3344.69 1705,3344.69 1744.37,3344.69 1665.63,3384.06 1705,3384.06 1744.37,3384.06
  other v2: 350,1550 2000,1550 350,1650 2000,1650 350,1750 2000,1750 350,1850 2000,1850 350,1950 2000,1950 535,3155
LO: R5.2 R21.2 U1.16 | length 3188.5
  Top Layer w13: R5.2 v1(1135,2540) ; R21.2 v1(1510,2540) ; v1(1535,3315) 1537.8,3312.2 U1.16
  Bottom Layer w13: 505,2760 505,2395 525,2375 1510,2375 v1@1510,2550 ; 510,2760 950,3200 ; 945,3200 1385.5,3200 1405,3219.5 1405,3290 v1(1435,3320) 1530,3320 v1(1535,3315) ; 1135,2375 v1@1135,2550
MODE: R12.1 R15.2 U1.13 | length 305.3
  Top Layer w13: R15.2 R12.1 1460,3470 1541.02,3388.98 U1.13
NetC1_1: C1.1 R1.1 | length 215
  Top Layer w30: R1.1@375,2905 C1.1
NetC18_1: C18.1 R17.2 | length 65
  Top Layer w13: C18.1 R17.2@1746.5,3620
NetQ1_4: Q1.4 R6.2 | length 100.3
  Top Layer w20: R6.2 505.78,2661.22 Q1.4
NetQ2_4: Q2.4 R5.1 | length 90.7
  Top Layer w20: Q2.4 1036.78,2437 R5.1@1125,2437
NetQ3_4: Q3.4 R21.1 | length 110.7
  Top Layer w13: Q3.4 1401.78,2437 R21.1
NetR19_2: R19.2 R20.2 | length 74.1
  Top Layer w13: R20.2 R19.2@1730.57,3740
OPT: R7.1 R8.2 U1.2 | length 303.8
  Top Layer w13: U1.2 1849.57,3235.43 1857.3,3227.7 1857.3,3218.7 1857.3,3050.8 R7.1@1856.5,3050 ; R7.1 R8.2
RES: C14.1 U1.14 | length 371.3
  Top Layer w13: C14.1 1320,3495 1380,3435 1465,3435 1536.61,3363.39 U1.14
SLOPE: R14.2 U1.12 | length 168.8
  Top Layer w13: R14.2 1530,3440 1555.43,3414.57 U1.12
SS: C16.1 U1.7 | length 313.5
  Top Layer w13: U1.7 1868.39,3363.39 1920,3415 1970,3415 1980,3425 1980,3503 C16.1
SW_N: R6.1 U1.19 | length 1313.4
  Top Layer w13: R6.1 508,2715 v1(555,2715) ; v1(1535,3216.5) 1553.94,3235.43 U1.19
  Bottom Layer w13: v1(555,2715) 990,3150 1425.01,3150 1499.88,3224.88 ; 1500,3224.76 1526.74,3224.76 v1(1535,3216.5)
SW_P: C1.2 C9.1 D1.1 L1.2 Q1.1 Q1.2 Q1.3 Q2.5 Q2.6 Q2.7 Q2.8 Q2.9 Q3.5 Q3.6 Q3.7 Q3.8 Q3.9 TP12.1 U1.18 | length 3943.4
  Top Layer w13: v1(555,2755) 650,2755 655,2750 Q1.3 Q1.2 Q1.1 Q2.9@875.35,2661.22 ; C9.1 1485,3236.02 1510,3261.02 v1(1535,3261.02) U1.18
  Top Layer w30: Q2.9 965.2,2581.77 965.2,2610.2 965.2,3040
  Top Layer w100: Q2.9 960,2605 965.2,2610.2 1237.25,2882.25 L1.2@1785,2882.25
  Bottom Layer w13: v1(555,2755) 560,2750 560,2760 978,3178 1413,3178 1487.76,3252.76 1526.74,3252.76 v1(1535,3261.02)
  Bottom Layer w30: 698.31,2806.69 716.62,2825 ; 865.81,2974.19 791.62,2900 ; TP12.1 791.62,2900 ; 716.62,2825 745,2825 750,2820 750,2858.38 ; 716.62,2825 750,2858.38 ; 750,2858.38 791.62,2900
  other v1: 900,2510 940,2510 980,2510 1020,2510 1265,2510 1305,2510 1345,2510 1385,2510 900,2550 940,2550 980,2550 1020,2550 1265,2550 1305,2550 1345,2550 1385,2550 900,2590 940,2590 980,2590 1020,2590 1265,2590 1305,2590 1345,2590 1385,2590 900,2630 940,2630 980,2630 1020,2630 1265,2630 1305,2630 1345,2630 1385,2630
SYN/RT: C12.1 R16.2 U1.8 | length 438.6
  Top Layer w13: U1.8 1864.28,3388.98 1911.3,3436 1941,3436 1955,3450 1955,3520 1982.5,3547.5 1982.5,3556.01 1990.99,3564.5 1999.5,3564.5 2012,3577 R16.2 C12.1
  other v1: 2012,3655
SYNC: U1.1 | length 54.9
  Top Layer w13: v1(1815,3155) 1815.24,3155.24 U1.1
UVLO: C13.1 R10.1 R13.2 TP9.1 U1.6 | length 796.5
  Top Layer w13: U1.6 1882.8,3337.8 1930,3385 v1(1950,3385) R13.2 2008.5,3456.5 C13.1 ; v1(2215,3385) R10.1 2257,3482 TP9.1
  Bottom Layer w13: v1(1950,3385) v1(2215,3385)
V+: C5.1 C6.1 C7.1 R2.1 R3.2 R9.1 R10.2 R11.2 TP1.1 TP5.1 | length 5100.3
  Top Layer w13: R9.1 R11.2 R10.2 v1(2370,3385)
  Top Layer w15: R3.2 v1(2120,3200)
  Top Layer w20: R2.1 v1(2545,2500)
  Top Layer w100: 2530.94,2400 2530.94,1780 2530.94,1555.94 2382.09,1407.09 2382.09,1350 2382.09,1175 2382.09,982.91 3022.91,342.09 TP1.1@3022.91,327.09
  Bottom Layer w13: v1(2370,3385) 2725,3030 2725,2385
  Bottom Layer w15: v1(2120,3200) 2140,3180 2495,3180 2680,2995 2680,2587.57 2637.43,2545 2555,2545 2545,2535 v1(2545,2500)
  other v2: 2775,1225 2925,1225 3075,1225 3225,1225 3375,1225 3525,1225
VCC: C11.2 D2.2 R7.2 R9.2 R12.2 U1.17 | length 1993.8
  Top Layer w11: C11.2@1485,3286.61 U1.17
  Top Layer w13: D2.2 v1(1435,3275) 1445,3285 1483,3285 C11.2 ; R12.2 v1(1460,3640) ; v1(1590,3060) R7.2@1800,3060 ; v1(2215,3240) R9.2
  MidLayer1 w13: v1(1435,3275) 1485,3325 1485,3367 1460,3392 v1(1460,3640) ; v1(1590,3060) 1853.05,3060 2030.75,3237.7 2212.7,3237.7 v1(2215,3240)
  Bottom Layer w13: v1(1435,3275) 1448.5,3288.5 1556.5,3288.5 1590,3255 v1(1590,3060)
VIN: C15.1 R11.1 U1.5 | length 517.1
  Top Layer w13: U1.5 v1(1945,3312.2) 1967.2,3290 C15.1 ; v1(2215,3315) R11.1
  Bottom Layer w13: v1(1945,3312.2) 2212.2,3312.2 v1(2215,3315)
VOUT: C2.1 C3.1 C4.1 C8.1 Q1.5 Q1.6 Q1.7 Q1.8 Q1.9 R1.2 R20.1 TP3.1 TP7.1 | length 8299.7
  Top Layer w20: v1(1540,3760) 1560,3740 R20.1
  Top Layer w60: R1.2@380,2702.36 380,2585 441.57,2523.43 Q1.9 680,2275 710,2245
  Top Layer w100: 710,2245 1011.06,1943.94 C3.1 C2.1 C4.1 1328.94,903.94 913,488 TP3.1@895,488
  Bottom Layer w20: TP3.1 515,350 380,485 170,485 85,570 85,3185 570,3670 745,3670 835,3760 v1(1540,3760)
  other v1: 620,2470 660,2470 700,2470 740,2470 620,2510 660,2510 700,2510 740,2510 620,2550 660,2550 700,2550 740,2550 620,2590 660,2590 700,2590 740,2590
  other v2: 575,1275 725,1275 875,1275 1025,1275
pads on no net: FID1.1 FID2.1 FID3.1 H1.1 H2.1 H3.1 H4.1 L1.3

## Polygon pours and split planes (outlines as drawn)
GND on Top Layer "Top Layer-SGND" (solid, remove dead copper, pour order 29): 1495,3336.65 1495,3380 1460,3415 1345,3415 1280,3480 1280,3580 1425,3580 1425,3660 1490,3660 1495,3655 1495,3575 1575,3575 1575,3655 1790,3655 1791.46,3653.54 1791.46,3600 1892.36,3600 1890,3535 1860,3520 1855,3425 1800,3425 1800,3405 1855,3405 1900,3450 1990,3450 1990,3670 2055,3670 2055,3237.7 2140,3237.7 2140,3090 1975,3090 1975,3025 2285,3025 2285,3790 2265,3810 1925,3810 1925,3800 1815,3690 1260,3690 1120,3550 1120,3240 1275,3240 1275,3275 1335,3335
CSPP_N on Top Layer "Top Layer-CSPP_N" (solid, remove dead copper, pour order 24): 2110,2645 2745,2645 2745,3005 2110,3005
VOUT on Top Layer "Top Layer-VOUT" (solid, remove dead copper, pour order 21): 840,2621.25 840,2355 1060,2160 1059.49,2055.51 1308.29,1800 1500,1800 1500,940.74 1230,665 1230,-10 451.62,-10 450,1265 690,1490 690,1860 495,1860 495,2825 700,2825 700,2622.28
GND on Top Layer "Top Layer-GND" (solid, remove dead copper, pour order 30): 3853.58,2485 3850,3960 -10,3960 -5,3955 0,3085 1310,3085 1315,3225 1100,3225 1100,3560 1260,3715 1464.17,3715 1564.17,3835 2340,3835 2375,3800 2375,3025 2760,3025 2760,2485
GND on Top Layer "Top Layer-GND" (solid, remove dead copper, pour order 22): -5.31,3185 600,3185 600,1833.24 665,1835 665,1495 440,1270 440,0 15,0 0,-15
V+ on Top Layer "Top Layer-V+" (solid, remove dead copper, pour order 25): 2329.06,2460 3850,2460 3850,-5 2605,-5 2605,635 2330,915
GND on Top Layer "Top Layer-GND" (solid, remove dead copper, pour order 20): 1200,2465 1365,2465 1365,2400 1485,2400 1485,2540 2030,2540 2030,3005 2100,3005 2100,2645 2300,2645 2300,915 2585,630 2585,0 1240,0 1240,630 1515,915 1515,1810 1352.89,1810 1080,2067.73 1080,2165 860,2350 860,2465 1000,2465 1000,2405 1200,2405
SW_P on Top Layer "Top Layer-SW_P" (solid, remove dead copper, pour order 27): 865,2485 1340,2485 1340,2560 2010,2560 2010,3000 1300,3000 1300,3079.5 640,3080 640,2640 865,2640
VOUT on Bottom Layer "Bottom Layer-VOUT" (solid, remove dead copper, pour order 26): 465,0 1120,0 1120,600 1225,705 1500,705 1500,1340 465,1340
V+ on Bottom Layer "Bottom Layer-V+" (solid, remove dead copper, pour order 28): 2610.94,2455 3855,2455 3855,0 2608.2,0 2612.03,636.17 2610,950 2610,1700
GND on Bottom Layer "Bottom Layer-GND" (solid, remove dead copper, pour order 23): 0,3962.55 2310,3960 3855,3960 3855,2460 2580.33,2460 2584.61,626.08 2585,-10 1135,-10 1135,585 1220,675 1515,675 1515,1355 435,1355 435,-5 0,-5
VOUT on MidLayer1 "MidLayer1-VOUT" (solid, remove dead copper, pour order 36): 465,1330 1225,1330 1225,0 465,0
GND on MidLayer1 "MidLayer1-GND" (solid, remove dead copper, pour order 33): 3855,3950 0,3950 0,1350 3855,1350
GND on MidLayer1 "MidLayer1-GND" (solid, remove dead copper, pour order 34): 0,0 450,0 450,2175 0,2175
V+ on MidLayer1 "MidLayer1-V+" (solid, remove dead copper, pour order 37): 3850,6.64 3850,1320 2600,1320 2600,-19.79
GND on MidLayer1 "MidLayer1-GND" (solid, remove dead copper, pour order 35): 2570,2225 2570,0 1250,0 1250,2225
GND on MidLayer2 "MidLayer2-No Net" (solid, remove dead copper, pour order 32): 0,-25 3855,-25 3850,3950 15,3950 0,3965

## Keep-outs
Keep-Out Layer:
  lines w10: -5,3960 -5,0 ; 0,3960 3850,3960 3850,-5 0,-5 ; -5,0 ccw(c0,0) 0,-5 ; -5,0 ccw(c0,0) 0,-5 ; -5,0 ccw(c0,0) 0,-5 ; -5,0 ccw(c0,0) 0,-5 ; -5,0 ccw(c0,0) 0,-5 ; -5,0 ccw(c0,0) 0,-5 ; 4950,3455 cw(c4950,3450) 4955,3450 ; 4950,3455 cw(c4950,3450) 4955,3450 ; 4950,3455 cw(c4950,3450) 4955,3450 ; 4950,3455 cw(c4950,3450) 4955,3450 ; 4950,3455 cw(c4950,3450) 4955,3450 ; 4950,3455 cw(c4950,3450) 4955,3450
  text ".Layer_Name" at 577,-858.49 h60

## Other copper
Top Layer:
  rectangle net SW_P: 545,2755 665,2853.5
  rectangle: 1125,-1225 1525,-775
  rectangle net GND: 1645,3165 1765,3490
  rectangle net SW_P: 1545,2340 2010,2615
  text ".Layer_Name" at 577,-858.49 h60
MidLayer1:
  rectangle net SW_P: 841.89,2402.76 1078.11,2695
  rectangle net SW_P: 1206.89,2402.76 1443.11,2695
  rectangle net VOUT: 561.89,2402.76 798.11,2685
  rectangle net SW_P: 841.89,2590 2075,3030
MidLayer2:
  rectangle net SW_P: 845,2402.76 1078.11,2697.24
  rectangle net SW_P: 1206.89,2402.76 1443.11,2697.24
Bottom Layer:
  rectangle net SW_P: 841.89,2390 1078.11,2697.24
  rectangle net SW_P: 1206.89,2390 1443.11,2697.24
  rectangle net VOUT: 561.89,2402.76 798.11,2690
  rectangle net SW_P: 845,2575 2025,2770
  rectangle net SW_P: 855,2750 2025,2990
  rectangle net SW_P: 685,2705 900,2820
  rectangle net SW_P: 775,2795 925,2910
  rectangle net SW_P: 740,2800 810,2875
  rectangle net SW_P: 820,2900 875,2955
  rectangle net SW_P: 1540,2115 2025,2645
  text ".Layer_Name" at 577,-858.49 h60

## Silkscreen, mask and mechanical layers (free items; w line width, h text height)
Top Overlay:
  text ".Pcb_File_Name_No_Path" at 150,1350 h70 r90
  text "©" at 3250,845 h105
  text ".CopyrightYear" at 3335,845 h60
  text "TI" at 3611,845 h60
  text "VOUT" at 675,50 h75
  text "GND" at 1825,50 h75
  text "VIN" at 2950,50 h75
  text ".Layer_Name" at 577,-858.49 h60
Bottom Overlay:
  rectangle: 2809,1990 3109,2090
  text ".PRJ_Number" at 3775,2000 h60
  text "-" at 3174,1989.5 h60
  text "MADE IN U.S." at 3775,1875 h60
  text "UL94V-0" at 3775,1750 h60
  text ".Layer_Name" at 577,-858.49 h60
Top Paste:
  text ".Layer_Name" at 577,-858.49 h60
Bottom Paste:
  text ".Layer_Name" at 577,-858.49 h60
Top Solder:
  text ".Layer_Name" at 577,-858.49 h60
  text ".Layer_Name" at 577,-858.49 h60
Bottom Solder:
  text ".Layer_Name" at 577,-858.49 h60
Drill Guide:
  text ".Layer_Name" at 577,-858.49 h60
M1 Board Outline:
  the board outline again, w10
  text ".Layer_Name" at 577,-858.49 h60
M2 Board Dimensions:
  rectangle: -0.5,-285.5 124.5,-160.5
  rectangle: 124.5,-410.5 499.5,-285.5
  lines w7: -0.5,-285.5 999.5,-285.5 ; 124.5,-410.5 124.5,-160.5 ; 249.5,-410.5 249.5,-160.5 ; 499.5,-410.5 499.5,-160.5 ; 749.5,-410.5 749.5,-160.5 ; -0.5,-410.5 999.5,-410.5 999.5,-160.5 -0.5,-160.5 -0.5,-410.5
  lines w10: -0.5,-475.5 -0.5,-455.5 ; 59.5,-485.5 -0.5,-465.5 ; 59.5,-445.5 -0.5,-465.5 ; 223.58,-465.5 -0.5,-465.5 ; 775.42,-465.5 999.5,-465.5 ; 939.5,-485.5 999.5,-465.5 ; 939.5,-445.5 999.5,-465.5 ; 999.5,-475.5 999.5,-455.5
  text "1000 (mil)" at 233.58,-501.49 h60
  text ".Layer_Name" at 577,-858.49 h60
M3 3D STEP Top:
  text ".Layer_Name" at 577,-858.49 h60
M4 3D STEP Bottom:
  text ".Layer_Name" at 577,-858.49 h60
M5 Assembly Top:
  lines w7: 5139,110.5 6264,110.5 ; 5139,233 6261.5,233 ; 5454,-9.5 5454,353 ; 5839,-9.5 5139,-9.5 ; 5839,353 5139,353 ; 5139,-9.5 6264,-9.5 6264,353 5139,353 ; 5139,-9.5 5139,353
  lines w10: -292,-930.17 6308,-930.17 ; -292,-726.83 6310,-726.83 ; -292,-523.5 -292,-1133.5 3713,-1133.5 6310,-1133.5 6310,-523.5 -291.5,-523.5 -291.5,-1133.5 1284,-1133.5 ; 2173,-1133.5 2173,-523.5 ; 3440,-726.83 3440,-523.5 ; 4280,-726.83 4280,-523.5 ; 4902,-1140 4902,-937.17
  text "TABLE 1" at 5526.5,388 h40
  text "Variant" at 5164,278 h40
  text "Label text" at 5599,278 h40
  text "001" at 5231.5,158 h40
  text "ChangeMe!" at 5509,155.5 h40
  text "002" at 5231.5,33 h40
  text "ChangeMe!" at 5504,30.5 h40
  text "COMPONENTS MARKED 'DNP' SHOULD NOT BE POPULATED, AND MAY NOT BE IN BILL OF MATERIALS" at 1153.5,-318.5 h60
  text "ASSEMBLY VARIANT:" at 1153,-434 h60
  text ".VariantName" at 2189,-434 h60
  text "PCB VIEWED FROM TOP SIDE" at -228.5,-655.67 h60
  text "BOARD #:" at 2248,-655.67 h60
  text ".PRJ_Number" at 2793.5,-655.67 h60
  text "REV:" at 3638,-655.67 h60
  text ".PCB_Rev" at 3929.5,-655.67 h60
  text "SVN REV:" at 4476,-655.67 h60
  text ".VersionControl_RevNumber" at 4982,-655.67 h60
  text "IGNORE ->" at -228.5,-858.49 h60
  text "PLOT NAME =" at -228.5,-1064.34 h60
  text ".plot_File_Name" at 577,-1064.34 h60
  text "GENERATED    :" at 2250,-1064.34 h60
  text ".Print_Date" at 3119.5,-1064.34 h60
  text ".Print_Time" at 3848.5,-1064.34 h60
  text "TEXAS INSTRUMENTS" at 5113,-1064.34 h60
M6 Assembly Bottom:
  lines w10: -292.5,-727.33 6309.5,-727.33 ; -290.5,-930.67 6309.5,-930.67 ; 1115.5,-1140.5 1115.5,-937.67 ; 1737.5,-727.33 1737.5,-524 ; 2577.5,-727.33 2577.5,-524 ; 3844.5,-1134 3844.5,-524 ; 4733.5,-1134 6309,-1134 6309,-524 -292.5,-524 -292.5,-1134 2304.5,-1134 6309.5,-1134 6309.5,-524
  text "COMPONENTS MARKED 'DNP' SHOULD NOT BE POPULATED, AND MAY NOT BE IN BILL OF MATERIALS" at 6102,-318 h60
  text ".VariantName" at 5058,-434 h60
  text "ASSEMBLY VARIANT:" at 6097,-434 h60
  text ".VersionControl_RevNumber" at 1035.5,-656.17 h60
  text "SVN REV:" at 1541.5,-656.17 h60
  text ".PCB_Rev" at 2088,-656.17 h60
  text "REV:" at 2379.5,-656.17 h60
  text ".PRJ_Number" at 3224,-656.17 h60
  text "BOARD #:" at 3769.5,-656.17 h60
  text "PCB VIEWED FROM BOTTOM SIDE" at 6246,-656.17 h60
  text "IGNORE ->" at 2547.85,-858.49 h60
  text "TEXAS INSTRUMENTS" at 904.5,-1064.84 h60
  text ".Print_Time" at 2169,-1064.84 h60
  text ".Print_Date" at 2898,-1064.84 h60
  text "GENERATED    :" at 3767.5,-1064.84 h60
  text ".plot_File_Name" at 5440.5,-1064.84 h60
  text "PLOT NAME =" at 6246,-1064.84 h60
M9 Title Sheet:
  drawing of 57 lines, arcs and shapes, not listed
  text "1" at 739.84,8036.5 h70
  text "2" at 3235.5,8036.5 h70
  text "3" at 5724.84,8036.5 h70
  text "4" at 8231.51,8036.5 h70
  text "5" at 10730.5,8036.5 h70
  text "6" at 13235.5,8036.5 h70
  text "A" at -416.5,6893.5 h70
  text "A" at 14383.5,6893.5 h70
  text "B" at -416.5,4513.5 h70
  text "B" at 14383.5,4513.5 h70
  text "C" at -416.5,2138.5 h70
  text "C" at 14383.5,2138.5 h70
  text "PROJECT TITLE:" at 11343.5,277.5 h45
  text ".PRJ_Title" at 11393.5,144.17 h70
  text "DESIGNED FOR:" at 11343.5,-23.5 h45
  text ".PRJ_Customer" at 11393.5,-163.5 h70
  text "D" at -416.5,-231.5 h70
  text "D" at 14383.5,-231.5 h70
  text "FILE NAME:" at 11343.5,-323.5 h45
  text ".PCB_File_Name_No_Path" at 11393.5,-443.5 h70
  text "Texas Instruments (TI) and/or its licensors do not warrant the accuracy or completeness of this specification" at 6374,-605.34 h45
  text "ENGINEER:" at 11343.5,-613.5 h45
  text "LAYOUT BY:" at 12848.5,-613.5 h45
  text "or any information contained therein. TI and/or its licensors do not warrant that this design will meet" at 6329.01,-718 h45
  text ".PRJ_Engineer" at 11393.5,-768.49 h70
  text ".PCB_Layout" at 12899,-768.49 h70
  text "the specifications, will be suitable for your application or fit for any particular purpose, or will operate in" at 6329.01,-830.67 h45
  text ".Layer_Name" at 577,-858.49 h60
  text "ALTIUM DESIGNER VERSION:" at 12848.5,-923.5 h45
  text "an implementation. TI and/or its licensors do not warrant that the design is production worthy. You should" at 6329.01,-943.33 h45
  text "completely validate and test your design implementation to confirm the system functionality for your application." at 6374,-1056 h45
  text ".print_Scale" at 11393.5,-1056.83 h70
  text ".Application_BuildNumber" at 12899,-1056.83 h70
  text "1" at 739.84,-1263.5 h70
  text "2" at 3235.5,-1263.5 h70
  text "3" at 5724.84,-1263.5 h70
  text "4" at 8231.51,-1263.5 h70
  text "5" at 10730.5,-1263.5 h70
  text "6" at 13235.5,-1263.5 h70
M10 Fab Notes:
  drawing of 203 lines, arcs and shapes, not listed
  text "DESIGN INFORMATION" at 12381.02,6810 h60
  text "(REFER ALSO ARRAY/PANEL PROFILING INFORMATION)" at 12019.46,6648.29 h60
  text "BOARD SIZE" at 11333.46,6644 h60
  text "3850MIL" at 11795.78,6516.18 h60
  text "X" at 12301.46,6516.18 h60
  text "3960MIL" at 12532.78,6516.18 h60
  text "Number of Layers :" at 11736.46,6319 h60
  text "4" at 12831.27,6309 h60
  text "MIN. TRACK WIDTH:" at 11736.46,6180 h60
  text "10" at 12832.7,6180 h60
  text "MIL" at 12987.46,6180 h60
  text "MIN. CLEARANCE:" at 11736.46,6048 h60
  text "8" at 12832.7,6048 h60
  text "MIL" at 12987.46,6048 h60
  text "MIN. VIA PAD SIZE:" at 11736.46,5916 h60
  text "24" at 12802.71,5916 h60
  text "MIL" at 12987.46,5916 h60
  text "0.05mm (2MIL)" at 12431.46,5774.29 h60
  text "MINIMUM ANNULAR RING" at 11407.23,5770 h60
  text "EXTERNAL" at 13139.46,5770 h60
  text "PER" at 11607.23,5652 h60
  text "IPC-D-275 CLASS 2 LEVEL C" at 11827.23,5652 h60
  text "MIL, HOLES" at 13315.46,5539.71 h60
  text "+/-" at 12923,5539 h60
  text "+/-" at 13777,5539 h60
  text "REGISTRATION TOLERANCES:" at 11407.23,5534 h60
  text "METAL" at 12607,5534 h60
  text "5" at 13183.2,5534 h60
  text "3" at 14016.2,5534 h60
  text "MIL" at 14132.46,5534 h60
  text "MATERIAL:" at 11332.46,5324.54 h60
  text "FR-4 High Tg" at 12318.9,5184.21 h60
  text "FR-4" at 11793.46,5175.64 h60
  text "OTHER" at 13241.46,5175.64 h60
  text "X" at 11600,5175 h60
  text "62 MIL (1.6mm) +/-10%" at 12073.56,5012.92 h60
  text "THICKNESS:" at 11407.23,5008.64 h60
  text "X" at 11945.4,5008.64 h60
  text "OTHER" at 13358.46,5008.64 h60
  text "TOLERANCE:" at 11407.23,4850.64 h60
  text "X" at 12246.53,4850.64 h60
  text "ANSI IPC-6012 TYPE 3 CLASS 2" at 12433.48,4850.64 h60
  text "OTHER +/-" at 12433.46,4694.64 h60
  text "BOW & TWIST:" at 11407.23,4537.64 h60
  text "X" at 12246.53,4537.64 h60
  text "ANSI IPC-6012 TYPE 3 CLASS 2" at 12433.48,4537.64 h60
  text "OTHER +/-" at 12433.46,4379.13 h60
  text "COPPER THICKNESS (FINISHED):" at 11332.46,4243.64 h60
  text "1.4MIL (1oz)" at 12212.46,4090.92 h60
  text "2MIL (1.4oz)" at 12979.46,4090.92 h60
  text "2.8MIL (2oz)" at 13706.46,4090.92 h60
  text "OUTER:" at 11689.46,4086.64 h60
  text "X" at 12084,4086 h60
  text "1.4MIL (1oz)" at 12562.46,3933.92 h60
  text "2.8MIL (2oz)" at 13406.46,3933.92 h60
  text "INNER SIGNAL:" at 11689.46,3929.64 h60
  text "X" at 12435.42,3929.64 h60
  text "DRILLING:" at 11332.46,3790.64 h60
  text "REFERENCE:" at 11407.23,3673.64 h60
  text "X" at 12055.46,3673.64 h60
  text "AS SHOWN" at 12242.46,3673.64 h60
  text "X" at 12956.46,3673.64 h60
  text "NC_DRILL FILES" at 13093.46,3673.64 h60
  text "PTH MIN COPPER THICKNESS:" at 11407.23,3515.64 h60
  text "X" at 12757.46,3515.64 h60
  text "1MIL" at 12894.46,3515.64 h60
  text "OTHER" at 13391.46,3515.64 h60
  text "BOARD FINISH:" at 11332.46,3356.64 h60
  text "SILKSCREEN:" at 11487.68,3238.64 h60
  text "X" at 12436.46,3238.64 h60
  text "TOP" at 12562.46,3238.64 h60
  text "X" at 12946.46,3238.64 h60
  text "BOTTOM" at 13073.46,3238.64 h60
  text "SILKSCREEN COLOR:" at 11487.68,3071.64 h60
  text "X" at 12435.42,3071.64 h60
  text "WHITE" at 12562.46,3071.64 h60
  text "OTHER" at 13073.46,3071.64 h60
  text "SOLDER RESIST COLOR:" at 11487.68,2901.64 h60
  text "X" at 12055.42,2742.44 h60
  text "GREEN" at 12182.46,2742.44 h60
  text "BLUE" at 12773.46,2742.44 h60
  text "OTHER" at 13311.46,2742.44 h60
  text "IMMERSION GOLD (ENIG)" at 12393.46,2553.92 h60
  text "SURFACE FINISH:" at 11332.46,2549.64 h60
  text "Pb-FREE HASL" at 13625.75,2549.64 h60
  text "X" at 12200,2400 h60
  text "HASL" at 12775.75,2399.64 h60
  text "OTHER" at 12393.46,2392.64 h60
  text "X" at 12200,2225 h60
  text "ARRAY/PANEL:" at 11332.46,2213.64 h60
  text "CUT AND TRIM PER MECH LAYER 1" at 12393.46,2209.35 h60
  text "N.C. ROUTE" at 12393.46,2057.64 h60
  text "V. SCORE" at 13259.46,2057.64 h60
  text "CERTIFICATION:" at 11332.46,1920.64 h60
  text "MATERIALS AND WORKMANSHIP FOR ALL PCBS" at 12057.46,1920.64 h60
  text "TO MEET OR EXCEED THE REQUIREMENTS OF:" at 12057.46,1822.64 h60
  text "X" at 11683.96,1686.13 h60
  text "ANSI IPC-A-600F CLASS ->" at 11822.96,1686.13 h60
  text "X" at 13462.02,1686.13 h60
  text "2" at 13580.96,1686.14 h60
  text "1" at 13265.96,1684.64 h60
  text "3" at 13934.96,1684.64 h60
  text "X" at 11686.02,1526.64 h60
  text "UL 94V-0" at 11822.96,1526.64 h60
  text "X" at 12498.02,1526.64 h60
  text "RoHS" at 12634.96,1526.64 h60
  text "OTHER" at 13279.36,1526.64 h60
  text "PER ORDER" at 13676.42,1526.64 h60
  text "ADDITIONAL REQUIREMENTS:" at 11332.46,1385.64 h60
  text "MICROSECTION:" at 11407.23,1270.64 h60
  text "YES" at 12312.96,1270.64 h60
  text "REQUIRED" at 13174.46,1114.49 h60
  text "BARE BOARD ELEC. TEST:" at 11407.23,1111.64 h60
  text "NONE" at 12712.96,1111.64 h60
  text "X" at 13047.46,1111.64 h60
  text "PER ORDER" at 13766.46,1111.64 h60
  text "MANUFACTURER'S ID/LOGO:" at 11407.23,954.64 h60
  text "RAIL" at 12872.96,950.35 h60
  text "METAL" at 13364.77,950.35 h60
  text "X" at 13750,950 h60
  text "SILK" at 13876.46,950.35 h60
  text ".Layer_Name" at 577,-858.49 h60
M11 Gerber Information:
  lines w10: -292,-930.17 6308,-930.17 ; -292,-726.83 6310,-726.83 ; -292,-523.5 -292,-1133.5 3713,-1133.5 6310,-1133.5 6310,-523.5 -291.5,-523.5 -291.5,-1133.5 1284,-1133.5 ; 2173,-1133.5 2173,-523.5 ; 3440,-726.83 3440,-523.5 ; 4280,-726.83 4280,-523.5 ; 4902,-1140 4902,-937.17
  text "ALL ARTWORK VIEWED FROM TOP SIDE" at -228.5,-655.67 h60
  text "BOARD #:" at 2248,-655.67 h60
  text ".PRJ_Number" at 2793.5,-655.67 h60
  text "REV:" at 3638,-655.67 h60
  text ".PCB_Rev" at 3929.5,-655.67 h60
  text "SVN REV:" at 4476,-655.67 h60
  text ".VersionControl_RevNumber" at 4982,-655.67 h60
  text "LAYER NAME =" at -228.5,-858.49 h60
  text "PLOT NAME =" at -228.5,-1064.34 h60
  text ".plot_File_Name" at 577,-1064.34 h60
  text "GENERATED    :" at 2250,-1064.34 h60
  text ".Print_Date" at 3119.5,-1064.34 h60
  text ".Print_Time" at 3848.5,-1064.34 h60
  text "TEXAS INSTRUMENTS" at 5113,-1064.34 h60
M12 Stackup:
  lines w8: 7320,7349 10400,7349 ; 7320,7504.6 10400,7504.6 ; 7260,6360 ccw(c7310,6360) 7310,6310 10410,6310 ccw(c10410,6360) 10460,6360 10460,7640 ccw(c10410,7640) 10410,7690 7310,7690 ccw(c7310,7640) 7260,7640 7260,6360
  text "Layer Stack Up Detail for: PMP7896 REVA.PcbDoc" at 7320,7548.5 h66
  text "Layer" at 7320,7446.6 h36
  text "Gerber" at 8412.39,7446.6 h36
  text "Copper" at 9025.34,7446.6 h36
  text "Dielectric" at 9697.07,7446.6 h36
  text "Name" at 7320,7374.6 h36
  text "Document" at 8412.39,7374.6 h36
  text "Thickness" at 9025.34,7374.6 h36
  text "Material" at 9697.07,7374.6 h36
  text "Top Solder Mask" at 7320,7273.12 h50
  text "(.GTS)" at 8412.39,7273.12 h50
  text "Solder Resist" at 9697.07,7273.12 h50
  text "Top Layer" at 7320,7129.38 h50
  text "(.GTL)" at 8412.39,7129.38 h50
  text "1.4mil" at 9025.34,7129.38 h50
  text "FR-4" at 9697.07,7057.5 h50
  text "MidLayer1" at 7320,6985.62 h50
  text "(.G1)" at 8412.39,6985.62 h50
  text "1.4mil" at 9025.34,6985.62 h50
  text "FR-4" at 9697.07,6913.75 h50
  text "MidLayer2" at 7320,6841.88 h50
  text "(.G2)" at 8412.39,6841.88 h50
  text "1.4mil" at 9025.34,6841.88 h50
  text "FR-4" at 9697.07,6770 h50
  text "Bottom Layer" at 7320,6698.12 h50
  text "(.GBL)" at 8412.39,6698.12 h50
  text "1.4mil" at 9025.34,6698.12 h50
  text "Bottom Solder Mask" at 7320,6554.38 h50
  text "(.GBS)" at 8412.39,6554.38 h50
  text "Solder Resist" at 9697.07,6554.38 h50
  text ".Layer_Name" at 577,-858.49 h60
M13 Component Bodies Top:
  text ".Layer_Name" at 577,-858.49 h60
M14 Component Bodies Bottom:
  text ".Layer_Name" at 577,-858.49 h60
M15 Courtyards Top:
  text ".Layer_Name" at 577,-858.49 h60
M16 Courtyards Bottom:
  text ".Layer_Name" at 577,-858.49 h60
Drill Drawing:
  text ".legend" at 4125,2875 h60
  text "Drill Table" at 4125,2650 h60
  text ".Layer_Name" at 577,-858.49 h60

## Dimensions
0,3960 to 0,0 on M2 Board Dimensions
3850,0 to 0,0 on M2 Board Dimensions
